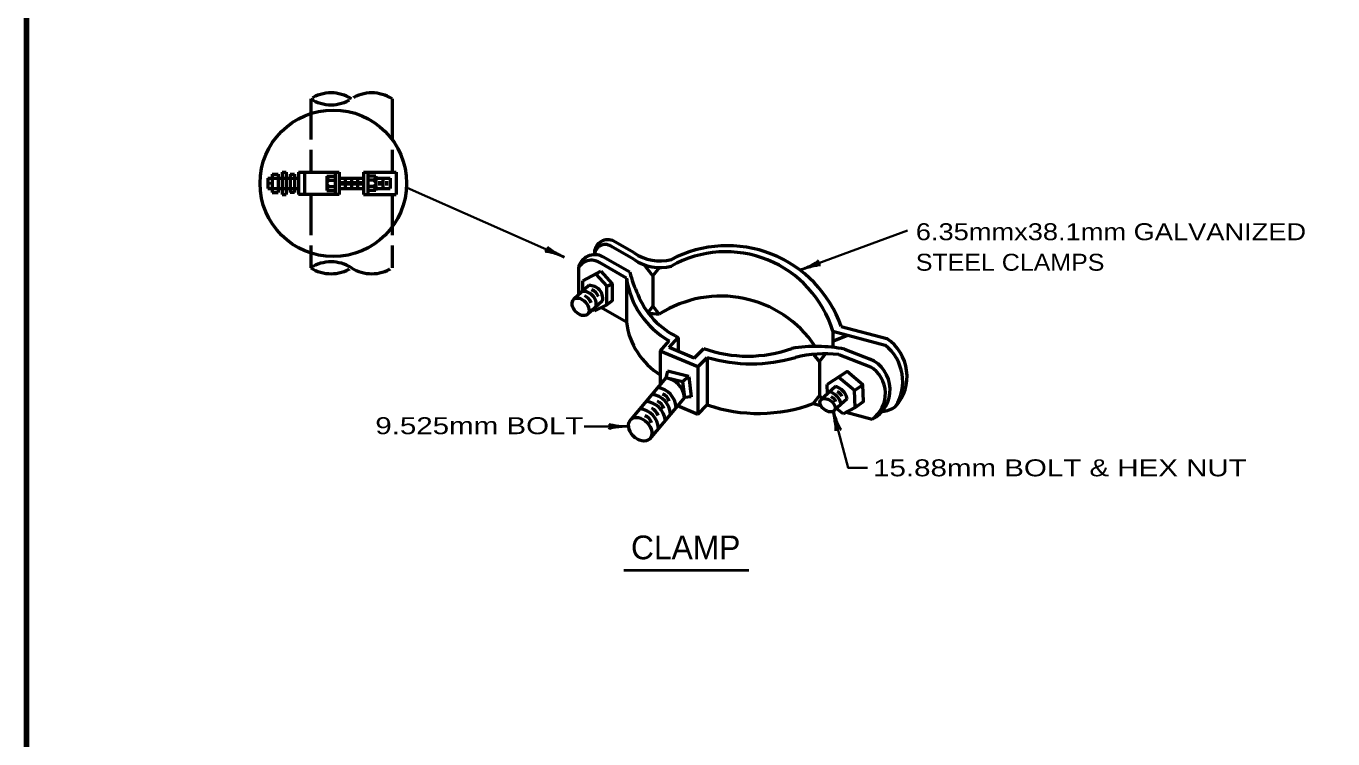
# Model space of a CAD drawing. Extents: x -32 to 824, y -12 to 532.
# Drawn here: x 25.8 to 256.9, y 139.3 to 265.4 of the extents above; entities that cross this region are included whole.
import ezdxf

# ---------------------------------------------------------------- set-up
doc = ezdxf.new("R2010")
doc.units = 0
doc.header["$LTSCALE"] = 1.2
doc.linetypes.add('LONG_DASHED', pattern=[7.5, 6, -1.5])
doc.layers.add('1', color=7, linetype='Continuous', lineweight=13)

msp = doc.modelspace()

# ---------------------------------------------------------------- linework, layer by layer
at = {"layer": '1', "linetype": 'LONG_DASHED', "lineweight": 53}
for p, q in [((76.093, 252.515), (76.093, 239.555)), ((90.493, 252.515), (90.493, 239.555)), ((76.093, 235.595), (76.093, 222.635)), ((90.493, 235.595), (90.493, 222.635))]:
    msp.add_line(p, q, dxfattribs=at)
at = {"layer": '1', "lineweight": 53}
for p, q in [((68.533, 238.475), (68.533, 236.675)), ((68.533, 238.475), (73.933, 238.475)), ((69.253, 239.195), (69.253, 235.955)), ((69.253, 239.195), (70.333, 239.195)), ((70.333, 239.195), (70.333, 235.955)), ((71.053, 239.555), (71.053, 235.595)), ((71.053, 239.555), (71.773, 239.555)), ((71.773, 239.555), (71.773, 235.595)), ((72.493, 239.195), (72.493, 235.955)), ((72.493, 239.195), (73.213, 239.195)), ((73.213, 239.195), (73.213, 235.955)), ((73.933, 239.555), (73.933, 235.595)), ((73.933, 239.555), (81.133, 239.555)), ((75.013, 239.555), (75.013, 235.595)), ((78.973, 238.835), (80.413, 238.835)), ((78.973, 238.835), (78.973, 236.315)), ((79.333, 238.115), (80.413, 238.115)), ((80.413, 239.555), (80.413, 235.595)), ((81.133, 239.555), (81.133, 235.595)), ((82.213, 238.475), (82.213, 236.675)), ((83.293, 238.475), (83.293, 236.675)), ((84.373, 238.475), (84.373, 236.675)), ((85.453, 239.555), (85.453, 235.595)), ((85.453, 239.555), (91.213, 239.555)), ((86.173, 239.555), (86.173, 235.595)), ((87.622, 238.835), (86.182, 238.835)), ((87.262, 238.115), (86.182, 238.115)), ((87.622, 238.835), (87.622, 236.315)), ((88.877, 238.475), (88.877, 236.675)), ((90.133, 238.475), (90.133, 236.675)), ((91.213, 239.555), (91.213, 235.595)), ((68.533, 236.675), (73.933, 236.675)), ((68.893, 237.755), (68.893, 237.395)), ((69.253, 235.955), (70.333, 235.955)), ((73.213, 235.955), (72.493, 235.955)), ((78.973, 236.315), (80.413, 236.315)), ((79.333, 237.035), (80.413, 237.035)), ((81.673, 237.935), (81.673, 237.215)), ((82.753, 237.935), (82.753, 237.215)), ((83.833, 237.935), (83.833, 237.215)), ((84.913, 237.935), (84.913, 237.215)), ((87.262, 237.035), (86.182, 237.035)), ((87.622, 236.315), (86.182, 236.315)), ((87.622, 237.395), (87.262, 237.035)), ((87.262, 237.035), (87.622, 236.675)), ((88.25, 237.935), (88.25, 237.215)), ((89.505, 237.935), (89.505, 237.215)), ((71.053, 235.595), (71.773, 235.595)), ((81.133, 235.595), (73.933, 235.595)), ((85.453, 235.595), (91.213, 235.595)), ((133.281, 225.252), (129.465, 227.433)), ((132.524, 221.851), (127.743, 224.584)), ((133.281, 224.098), (129.465, 226.279)), ((123.448, 222.569), (123.448, 217.799)), ((127.429, 222.009), (124.25, 220.319)), ((131.929, 220.809), (127.148, 223.542)), ((136.622, 221.226), (135.103, 223.171)), ((136.622, 221.226), (137.767, 222.691)), ((124.25, 218.522), (124.25, 220.319)), ((126.528, 221.53), (128.453, 219.392)), ((131.929, 220.809), (131.929, 213.009)), ((125.307, 219.473), (122.631, 217.064)), ((127.716, 216.797), (125.04, 214.389)), ((126.058, 215.305), (126.296, 215.039)), ((131.929, 213.009), (127.419, 215.587)), ((136.622, 215.826), (137.731, 214.408)), ((136.058, 214.627), (137.731, 214.408)), ((139.489, 208.546), (141.095, 210.329)), ((141.095, 210.329), (141.095, 207.864)), ((168.42, 211.429), (177.693, 208.944)), ((168.42, 211.429), (168.42, 208.552)), ((168.57, 209.701), (171.045, 210.725)), ((169.89, 212.277), (178.004, 210.103)), ((137.915, 207.91), (139.521, 209.693)), ((143.907, 206.67), (139.489, 208.546)), ((143.907, 206.67), (145.604, 208.367)), ((170.532, 208.221), (175.016, 206.501)), ((144.543, 205.097), (137.915, 207.91)), ((137.915, 207.91), (137.915, 201.981)), ((144.543, 205.097), (146.24, 206.794)), ((146.24, 206.794), (146.24, 198.394)), ((166.09, 206.05), (165.102, 207.315)), ((166.09, 206.05), (167.149, 207.406)), ((166.09, 206.05), (166.09, 200.05)), ((169.49, 207.292), (175.091, 205.142)), ((139.186, 204.327), (138.905, 203.161)), ((142.978, 203.413), (139.186, 204.327)), ((142.978, 203.413), (141.878, 202.444)), ((142.978, 203.413), (143.376, 199.835)), ((144.543, 205.097), (144.543, 196.697)), ((138.905, 203.161), (132.734, 195.807)), ((141.878, 202.444), (138.905, 203.161)), ((141.878, 202.444), (142.183, 199.703)), ((168.905, 201.667), (166.272, 199.212)), ((167.512, 200.368), (167.456, 201.981)), ((172.262, 200.922), (169.504, 203.236)), ((142.183, 199.703), (136.012, 192.349)), ((143.376, 199.835), (142.183, 199.703)), ((166.09, 200.05), (164.982, 198.632)), ((166.09, 200.05), (166.546, 199.467)), ((170.951, 199.473), (168.757, 197.427)), ((144.543, 196.697), (140.943, 198.225)), ((144.543, 196.697), (146.24, 198.394)), ((164.982, 198.632), (166.299, 198.279)), ((170.247, 196.797), (169.108, 197.754)), ((170.777, 197.079), (175.413, 195.837))]:
    msp.add_line(p, q, dxfattribs=at)
at = {"layer": '1', "lineweight": 35}
for p, q in [((93.15, 236.782), (120.896, 224.537)), ((162.881, 222.316), (181.65, 229.255)), ((132.279, 194.561), (124.46, 194.561))]:
    msp.add_line(p, q, dxfattribs=at)
at = {"layer": '1', "lineweight": 40}
msp.add_line((131.504, 169.174), (153.602, 169.174), dxfattribs=at)
at = {"layer": '1', "lineweight": 158}
msp.add_lwpolyline([(817.469, 525.227), (25.769, 525.127), (25.869, -0.873)], dxfattribs=at)
at = {"layer": '1', "lineweight": 53}
for points in [[(78.973, 238.475), (79.333, 238.115), (78.973, 237.755)], [(81.133, 238.475), (82.213, 238.475), (83.293, 238.475), (84.373, 238.475), (85.453, 238.475)], [(87.622, 238.475), (87.262, 238.115), (87.622, 237.755)], [(87.622, 238.475), (88.877, 238.475), (90.133, 238.475)], [(78.973, 237.395), (79.333, 237.035), (78.973, 236.675)], [(81.133, 236.675), (83.293, 236.675), (85.453, 236.675)], [(87.622, 236.675), (88.877, 236.675), (90.133, 236.675)], [(127.429, 222.009), (129.436, 219.78), (129.436, 216.78), (128.453, 216.091), (126.296, 215.039)], [(128.453, 216.091), (128.453, 219.392), (129.436, 219.78)], [(136.622, 221.226), (136.622, 215.826), (135.87, 214.863)], [(170.247, 196.797), (172.366, 197.924), (173.841, 198.957), (173.736, 201.955), (170.978, 204.269), (167.456, 201.981)], [(172.366, 197.924), (172.262, 200.922), (173.736, 201.955)]]:
    msp.add_lwpolyline(points, dxfattribs=at)
at = {"layer": '1', "lineweight": 35}
msp.add_lwpolyline([(168.529, 197.228), (171.129, 187.27), (174.59, 187.27)], dxfattribs=at)
at = {"layer": '1', "lineweight": 53}
msp.add_circle((80.092, 237.581), 12.96, dxfattribs=at)
at = {"layer": '1', "linetype": 'LONG_DASHED', "lineweight": 53}
for centre, start, end in [((79.693, 246.88), 57.42639, 122.57361), ((79.693, 258.15), 237.42639, 302.57361), ((86.893, 246.88), 57.42639, 122.57361), ((79.693, 217), 57.42639, 122.57361), ((79.693, 228.27), 237.42639, 302.57361), ((86.893, 228.27), 237.42639, 302.57361)]:
    msp.add_arc(centre, 6.687, start, end, dxfattribs=at)
at = {"layer": '1', "lineweight": 53}
for centre, radius, start, end in [((128.625, 225.247), 2.342, 68.98454, 184.96528), ((128.2, 224.834), 1.92, 48.79801, 173.73367), ((149.785, 205.24), 21.3, 19.29143, 117.70819), ((126.328, 222.013), 2.934, 61.16852, 169.07366), ((137.925, 232.358), 8.489, 236.83956, 283.32479), ((149.535, 205.747), 19.721, 16.7434, 119.30902), ((125.725, 221.428), 2.547, 56.06469, 153.37669), ((137.863, 230.85), 8.16, 235.84201, 284.32234), ((146.989, 222.944), 15.21, 188.06983, 240.59731), ((157.613, 228.673), 26, 195.21089, 204.37149), ((124.323, 216.17), 2.272, 349.61263, 94.38617), ((123.78, 215.711), 2.074, 20.88408, 69.09679), ((125.48, 217.207), 2.272, 349.61263, 94.38617), ((125.032, 216.815), 2.074, 20.88408, 69.09679), ((147.203, 223.253), 14.295, 201.80286, 244.70416), ((148.637, 197.516), 20.107, 33.86522, 122.8499), ((144.685, 214.644), 12.86, 187.30417, 238.23787), ((153.404, 230.101), 23.091, 250.25742, 289.74258), ((165.471, 182.83), 25.891, 78.72641, 99.48511), ((172.543, 202.485), 8.261, 327.83586, 51.43283), ((173.526, 203.427), 8.039, 318.38164, 56.15447), ((154.04, 232.745), 27.099, 253.27137, 286.72862), ((167.176, 183.871), 23.535, 84.35687, 103.10294), ((172.663, 201.073), 5.915, 297.71146, 66.56345), ((172.147, 200.382), 5.597, 305.70046, 58.26699), ((136.94, 197.685), 3.801, 4.32722, 81.54855), ((138.395, 199.394), 3.801, 4.65558, 82.27962), ((168.144, 198.906), 2.864, 11.41742, 74.57891), ((135.049, 195.211), 3.801, 7.29827, 83.92311), ((135.959, 196.484), 3.801, 4.74535, 82.35434), ((136.775, 197.302), 1.822, 14.18506, 70.66849), ((137.72, 198.575), 1.822, 14.18506, 70.66849), ((167.113, 197.923), 2.864, 11.41742, 74.57891), ((167.404, 198.293), 1.705, 21.50211, 64.13038), ((168.446, 199.247), 1.705, 21.50211, 64.13038), ((133.85, 193.938), 3.801, 5.19441, 82.73082), ((134.593, 194.756), 1.822, 14.18506, 70.66849), ((135.757, 196.066), 1.822, 14.18506, 70.66849), ((155.279, 224.59), 27.712, 250.96338, 290.4942), ((176.947, 201.715), 4.456, 273.11257, 305.52158)]:
    msp.add_arc(centre, radius, start, end, dxfattribs=at)
at = {"layer": '1', "lineweight": 40}
for centre, major_axis, ratio, start_param, end_param in [((119.564, 224.762), (2.036, -0.694), 0.122415, 0.8963533, 3.1415927), ((119.768, 225.312), (-1.843, 1.044), 0.07063, 6.2823074, 8.5597026), ((163.994, 223.081), (-1.945, -0.919), 0.122415, 0.8963533, 3.1415927), ((163.994, 223.081), (-1.945, -0.919), 0.122415, 0.8963533, 3.1415927), ((164.23, 222.544), (-2.05, -0.533), 0.07063, 3.1407148, 5.41811), ((164.23, 222.544), (-2.05, -0.533), 0.07063, 3.1407148, 5.41811), ((168.623, 195.862), (-0.328, 2.093), 0.07063, 3.1407148, 5.41811), ((169.181, 196.044), (-0.723, 2.026), 0.122415, 0.8963533, 3.1415927), ((130.969, 194.23), (2.143, 0.187), 0.122415, 0.8963533, 3.1415927), ((130.934, 194.815), (2.108, -0.211), 0.07063, 3.1407148, 5.41811)]:
    msp.add_ellipse(centre, major_axis=major_axis, ratio=ratio, start_param=start_param, end_param=end_param, dxfattribs=at)
at = {"layer": '1', "lineweight": 53}
for centre, major_axis, ratio in [((123.836, 215.726), (1.204, -1.338), 0.663346), ((167.515, 198.319), (1.242, -0.892), 0.624582), ((134.373, 194.078), (1.639, -1.729), 0.71432)]:
    msp.add_ellipse(centre, major_axis=major_axis, ratio=ratio, dxfattribs=at)

# ---------------------------------------------------------------- texts
at = {"layer": '1'}
for s, width, p in [('6.35mmx38.1mm GALVANIZED', 1.2, (183.121, 227.512)), ('STEEL CLAMPS', 1.1, (183.121, 222.112)), ('9.525mm BOLT', 1.3, (87.524, 193.204)), ('15.88mm BOLT & HEX NUT', 1.3, (175.567, 185.751))]:
    msp.add_text(s, height=3, dxfattribs=dict(at, width=width)).set_placement(p)
msp.add_text('CLAMP', height=4.2, dxfattribs=at).set_placement((132.744, 171.077))

doc.saveas('drawing.dxf')
